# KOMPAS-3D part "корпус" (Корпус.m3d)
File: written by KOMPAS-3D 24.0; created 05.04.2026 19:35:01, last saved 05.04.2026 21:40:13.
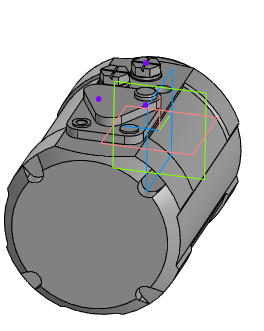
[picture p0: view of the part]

Document properties: Автор: R2D2; Полное имя файла: E:\Работа\Зайцев\Аксессуары для пневмоприводов\Электропневматические позиционеры DN.ru\ЭИП Электропневматический позиционер DN.ru\ЭИП-1500 Электропневматический позиционер DN.ru\5-25\Корпус.m3d

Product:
- Part/product: корпус
    Масса: 7.921649
    Раздел спецификации: Прочие изделия
    Примечание: D900-02741

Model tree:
1. Эскиз:1
2. Элемент вращения:1
     Угол 1 = 360
3. Эскиз:2  (with: Грань.Элемент вращения:1)
4. Элемент выдавливания:1
     Расстояние 2 = 139
5. Фаска:2  (with: Ребро.Элемент выдавливания:1)
     Угол = 45; Длина 1 = 4; Длина 2 = 4
6. Массив по концентрической сетке:1  (with: Элемент выдавливания:1, Эскиз:2, Фаска:2, Грань.Элемент вращения:1)  (3 pattern instances)
     Шаг 2 = 90
7. Эскиз:3  (with: Грань.Элемент вращения:1, Ребро.Элемент вращения:1)
8. Элемент выдавливания:2
     Расстояние 2 = 139
9. Эскиз:4  (with: Ребро.Элемент выдавливания:2, Ребро.Элемент вращения:1)
10. Элемент вращения:2
     Угол 1 = 360
11. Скругление:1  (with: Ребро.Элемент вращения:2)
     Радиус = 2
12. Эскиз:5  (with: Грань.Элемент вращения:1)
13. Элемент выдавливания:3
     Расстояние 2 = 7.5
14. Массив по концентрической сетке:2  (with: Элемент выдавливания:3, Эскиз:5)  (4 pattern instances)
     Шаг 2 = 360
15. Эскиз:6  (with: Грань.Элемент выдавливания:2, Ребро.Элемент выдавливания:2, Вершина.Элемент вращения:2)
16. Элемент выдавливания:4
     Расстояние 2 = 10
17. Эскиз:7  (with: Грань.Элемент выдавливания:2)
18. Элемент выдавливания:6
     Расстояние 2 = 10
19. Эскиз:8  (with: Грань.Элемент выдавливания:2, Ребро.Элемент выдавливания:6)
20. Элемент выдавливания:7
     Расстояние 1 = 2
21. Скругление:2  (with: Ребро.Элемент выдавливания:7)
     Радиус = 0.5
22. Эскиз:9  (with: Грань.Элемент выдавливания:7, Ребро.Скругление:2, Ребро.Элемент выдавливания:7)
23. Элемент выдавливания:8
     Расстояние 1 = 5
24. Эскиз:10  (with: Грань.Элемент выдавливания:8, Ребро.Элемент выдавливания:7)
25. Элемент выдавливания:9
     Расстояние 2 = 2
26. Массив по концентрической сетке:3  (with: Элемент выдавливания:9, Грань.Элемент выдавливания:7)  (4 pattern instances)
     Шаг 2 = 360
27. Точка:1  (with: Грань.Элемент выдавливания:8)
     X = 52; Y = -30
28. Массив по точкам:1
29. Экземпляр ( 1 )  (with: Массив по концентрической сетке:3, Элемент выдавливания:9)
30. Экземпляр ( 2 )  (with: Элемент выдавливания:9)
31. Экземпляр ( 3 )  (with: Элемент выдавливания:9)
32. Экземпляр ( 4 )  (with: Элемент выдавливания:9)
33. Эскиз:11  (with: Грань.Элемент выдавливания:2, Ребро.Элемент выдавливания:2, Ребро.Элемент выдавливания:4)
34. Элемент выдавливания:10
     Расстояние 1 = 5
35. Элемент выдавливания:11
     Расстояние 1 = 2
36. Скругление:3  (with: Ребро.Элемент выдавливания:10)
     Радиус = 8
37. Точка:2  (with: Ребро.Скругление:3)
     X = 50; Y = -77.5; Z = -12.7945
38. Точка:3  (with: Ребро.Скругление:3)
     X = 50; Y = -77.5; Z = 12.7945
39. Эскиз:13  (with: Грань.Элемент выдавливания:10, Вершина.Скругление:3, Ребро.Элемент выдавливания:10)
40. Элемент выдавливания:13
     Расстояние 1 = 5
41. Эскиз:14  (with: Грань.Элемент выдавливания:10, Ребро.Элемент выдавливания:10)
42. Элемент выдавливания:14
     Расстояние 1 = 1
43. Эскиз:15  (with: Грань.Элемент выдавливания:14, Ребро.Элемент выдавливания:14)
44. Элемент выдавливания:15
     Расстояние 2 = 0.5
45. Эскиз:16  (with: Грань.Элемент выдавливания:13)
46. Элемент выдавливания:16
     Расстояние 1 = 3
47. Скругление:4  (with: Ребро.Элемент выдавливания:16)
     Радиус = 1

Expressions: 45+22.5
